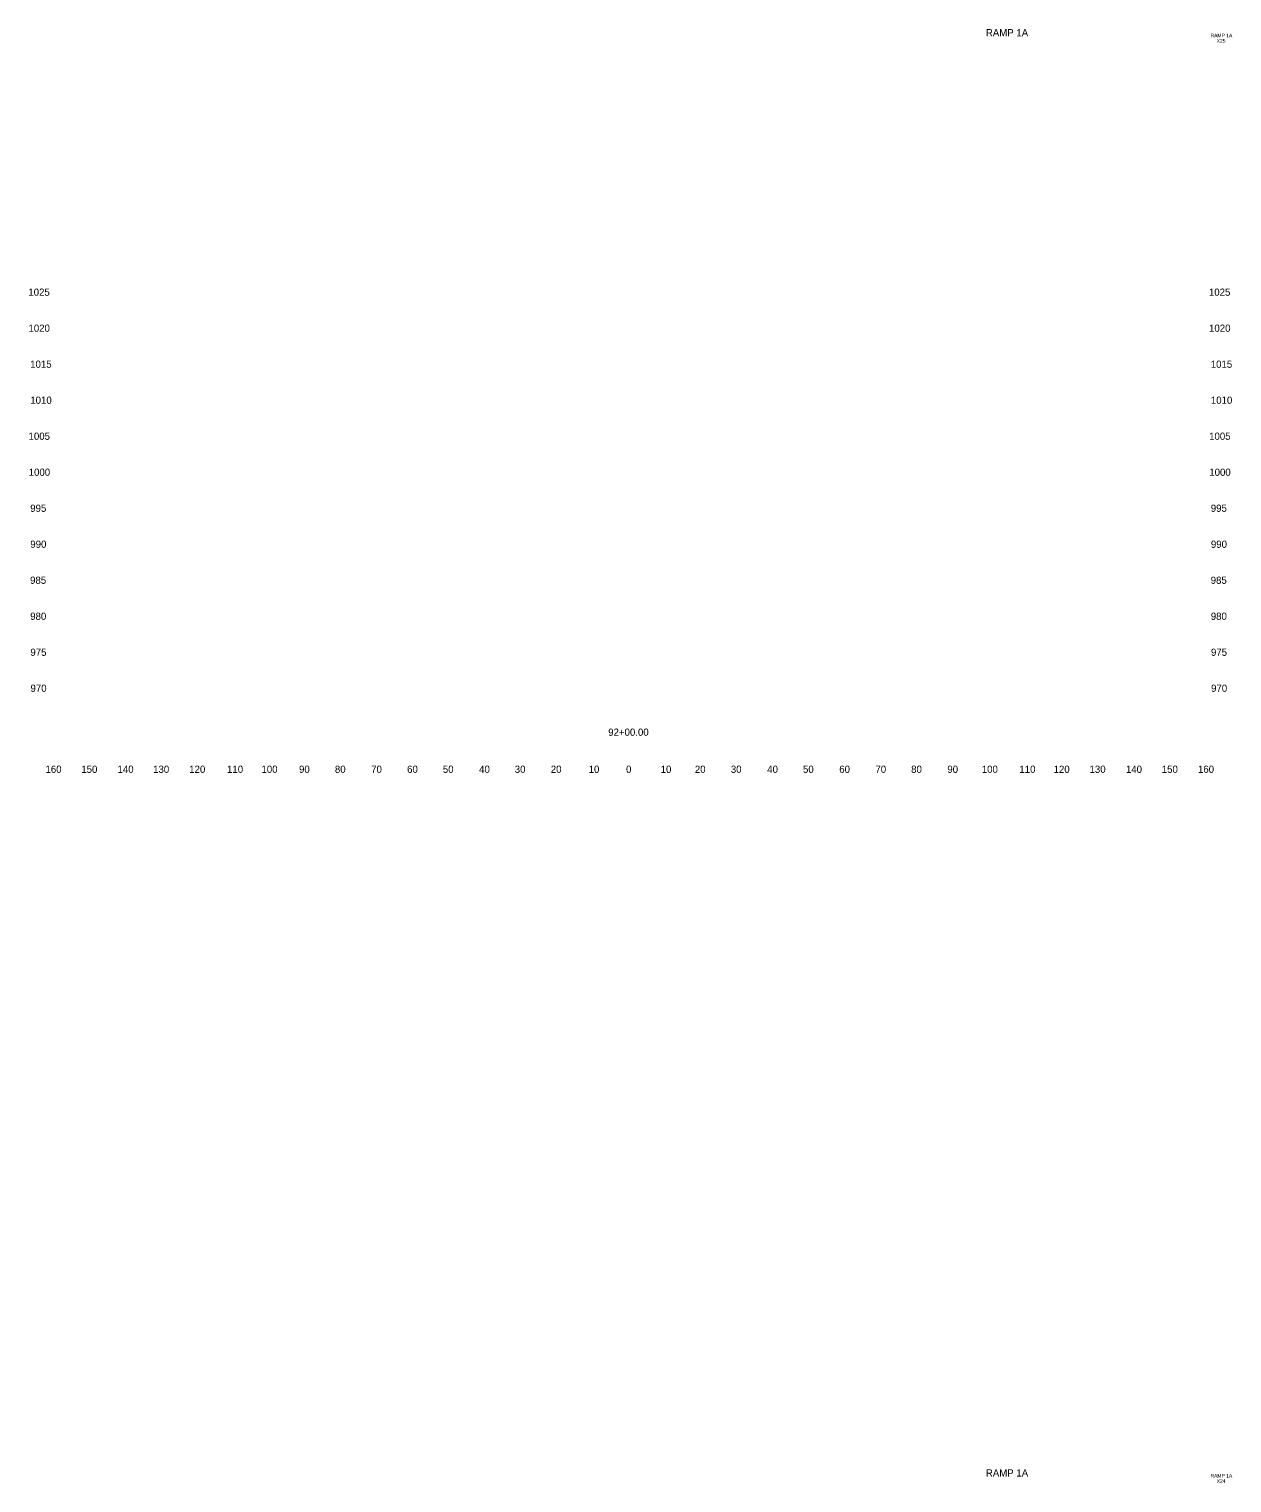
# Model space of a CAD drawing. Extents: x 4994 to 6873, y 4997 to 8804.
# Drawn here: x 6023.5 to 6357.5, y 6400.3 to 6804.1 of the extents above; entities that cross this region are included whole.
import ezdxf

# ---------------------------------------------------------------- set-up
doc = ezdxf.new("R2010")
doc.units = 0
for name, color, linetype in [('RD_SHT_ID', 7, 'Continuous'), ('RD_XS_TX_Offset', 7, 'Continuous'), ('RD_XS_TX_Station', 7, 'Continuous')]:
    doc.layers.add(name, color=color, linetype=linetype)

msp = doc.modelspace()

# ---------------------------------------------------------------- texts
at = {"layer": 'RD_SHT_ID'}
for s, height, p in [('RAMP 1A', 2, (6289.21, 6802.06)), ('RAMP 1A', 1, (6351.57, 6801.8)), ('X25', 1, (6353.29, 6800.3)), ('RAMP 1A', 2, (6289.21, 6402.06)), ('RAMP 1A', 1, (6351.57, 6401.8)), ('X24', 1, (6353.29, 6400.3))]:
    msp.add_text(s, height=height, dxfattribs=at).set_placement(p)
at = {"layer": 'RD_XS_TX_Offset'}
for s, p in [('1025', (6023.34, 6730)), ('1025', (6351.14, 6730)), ('1020', (6023.37, 6720)), ('1020', (6351.17, 6720)), ('1015', (6023.85, 6710)), ('1015', (6351.65, 6710)), ('1010', (6023.88, 6700)), ('1010', (6351.68, 6700)), ('1005', (6023.4, 6690)), ('1005', (6351.2, 6690)), ('1000', (6023.44, 6680)), ('1000', (6351.24, 6680)), ('995', (6023.86, 6670)), ('995', (6351.66, 6670)), ('990', (6023.89, 6660)), ('990', (6351.69, 6660)), ('985', (6023.83, 6650)), ('985', (6351.63, 6650)), ('980', (6023.86, 6640)), ('980', (6351.66, 6640)), ('975', (6023.91, 6630)), ('975', (6351.71, 6630)), ('970', (6023.94, 6620)), ('970', (6351.74, 6620)), ('160', (6028.1, 6597.5)), ('150', (6038.04, 6597.5)), ('140', (6048.1, 6597.5)), ('130', (6057.99, 6597.5)), ('120', (6068.01, 6597.5)), ('110', (6078.51, 6597.5)), ('100', (6088.07, 6597.5)), ('90', (6098.5, 6597.5)), ('80', (6108.46, 6597.5)), ('70', (6118.54, 6597.5)), ('60', (6128.5, 6597.5)), ('50', (6138.43, 6597.5)), ('40', (6148.5, 6597.5)), ('30', (6158.39, 6597.5)), ('20', (6168.4, 6597.5)), ('10', (6178.91, 6597.5)), ('0', (6189.3, 6597.5)), ('0', (6189.3, 6597.5)), ('10', (6198.91, 6597.5)), ('20', (6208.4, 6597.5)), ('30', (6218.39, 6597.5)), ('40', (6228.5, 6597.5)), ('50', (6238.43, 6597.5)), ('60', (6248.5, 6597.5)), ('70', (6258.54, 6597.5)), ('80', (6268.46, 6597.5)), ('90', (6278.5, 6597.5)), ('100', (6288.07, 6597.5)), ('110', (6298.51, 6597.5)), ('120', (6308.01, 6597.5)), ('130', (6317.99, 6597.5)), ('140', (6328.1, 6597.5)), ('150', (6338.04, 6597.5)), ('160', (6348.1, 6597.5))]:
    msp.add_text(s, height=2, dxfattribs=at).set_placement(p)
at = {"layer": 'RD_XS_TX_Station'}
msp.add_text('92+00.00', height=2, dxfattribs=at).set_placement((6184.35, 6607.8))

doc.saveas('drawing.dxf')
